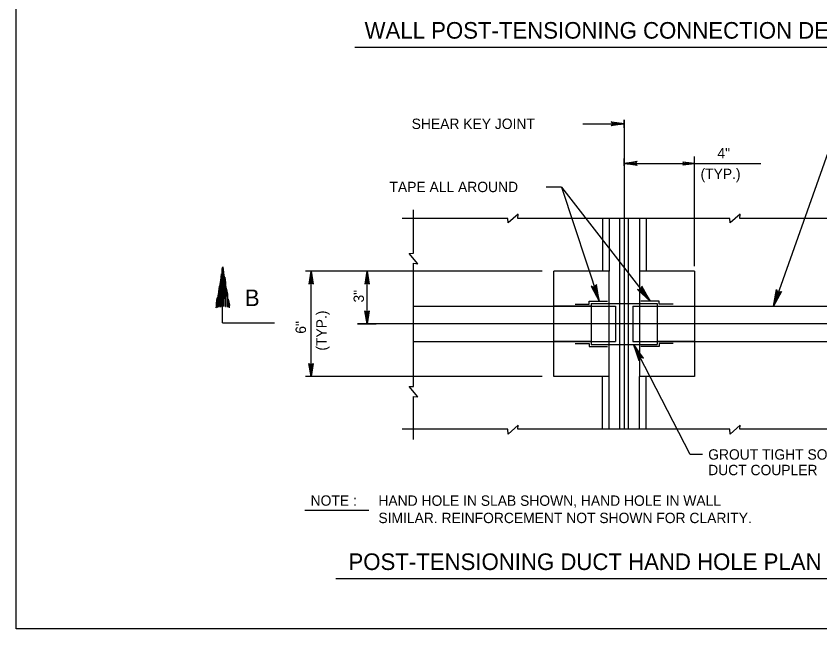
# Model space of a CAD drawing. Extents: x 641328 to 643024, y 298283 to 300065.
# Drawn here: x 642208.5 to 642441.2, y 298892.3 to 299069.6 of the extents above; entities that cross this region are included whole.
import ezdxf

# ---------------------------------------------------------------- set-up
doc = ezdxf.new("R2010")
doc.units = 0
doc.layers.add('2', color=7, linetype='Continuous')
doc.layers.add('Default', color=7, linetype='Continuous')

msp = doc.modelspace()

# ---------------------------------------------------------------- linework, layer by layer
at = {"layer": '2'}
for p, q in [((642208.51, 298892.3), (642208.51, 299456.3)), ((642306.6, 299060.56), (642498.06, 299060.56)), ((642384.54, 299039.59), (642384.54, 298950.05)), ((642372.57, 299038.42), (642384.54, 299038.42)), ((642380.93, 299038.85), (642380.74, 299039.01)), ((642380.74, 299039.01), (642384.54, 299038.42)), ((642384.54, 299038.42), (642380.74, 299037.79)), ((642380.74, 299037.79), (642380.94, 299037.96)), ((642380.93, 299038.85), (642381.06, 299038.59)), ((642384.54, 299038.42), (642380.93, 299038.85)), ((642380.94, 299037.96), (642384.54, 299038.42)), ((642381.07, 299038.23), (642380.94, 299037.96)), ((642381.06, 299038.59), (642384.54, 299038.42)), ((642381.06, 299038.59), (642381.07, 299038.23)), ((642384.54, 299038.42), (642381.06, 299038.41)), ((642384.54, 299038.42), (642381.07, 299038.23)), ((642443.48, 299030.02), (642427.76, 298985.61)), ((642404.86, 298997.23), (642404.86, 299028.92)), ((642384.54, 299026.92), (642388.33, 299027.55)), ((642388.14, 299027.38), (642384.54, 299026.92)), ((642384.54, 299026.92), (642388.01, 299027.12)), ((642384.54, 299026.92), (642388.01, 299026.93)), ((642384.54, 299026.92), (642424.12, 299026.92)), ((642388.01, 299026.75), (642384.54, 299026.92)), ((642384.54, 299026.92), (642388.15, 299026.49)), ((642388.34, 299026.33), (642384.54, 299026.92)), ((642388.01, 299027.12), (642388.14, 299027.38)), ((642388.01, 299026.75), (642388.01, 299027.12)), ((642388.15, 299026.49), (642388.01, 299026.75)), ((642388.33, 299027.55), (642388.14, 299027.38)), ((642388.15, 299026.49), (642388.34, 299026.33)), ((642366.39, 299020.08), (642377.29, 298987.09)), ((642366.39, 299020.08), (642392.02, 298987.09)), ((642323.58, 299000.94), (642323.58, 299013.53)), ((642350.88, 299011.01), (642320.28, 299011.01)), ((642415.14, 299011.01), (642353.77, 299011.01)), ((642378.28, 299011.01), (642378.28, 298995.77)), ((642380.19, 299011.01), (642380.19, 298995.77)), ((642383.27, 298986.45), (642383.27, 299011.01)), ((642385.81, 298986.45), (642385.81, 299011.01)), ((642388.98, 299011.01), (642388.98, 298995.77)), ((642390.89, 299011.01), (642390.89, 298995.77)), ((642448.79, 299011.01), (642418.02, 299011.01)), ((642323.58, 298962.42), (642323.58, 298998.05)), ((642268.29, 298980.82), (642268.29, 298995.86)), ((642360.81, 298995.77), (642292.3, 298995.77)), ((642293.33, 298991.97), (642293.92, 298995.77)), ((642293.92, 298995.77), (642293.49, 298992.16)), ((642293.75, 298992.29), (642293.92, 298995.77)), ((642293.92, 298965.29), (642293.92, 298995.77)), ((642293.92, 298995.77), (642294.12, 298992.3)), ((642294.38, 298992.17), (642293.92, 298995.77)), ((642293.92, 298995.77), (642294.55, 298991.97)), ((642293.92, 298995.77), (642293.94, 298992.3)), ((642309.52, 298991.97), (642310.11, 298995.77)), ((642310.11, 298995.77), (642309.68, 298992.16)), ((642309.95, 298992.29), (642310.11, 298995.77)), ((642310.11, 298980.53), (642310.11, 298995.77)), ((642310.11, 298995.77), (642310.31, 298992.3)), ((642310.57, 298992.17), (642310.11, 298995.77)), ((642310.11, 298995.77), (642310.75, 298991.97)), ((642310.11, 298995.77), (642310.13, 298992.3)), ((642364.22, 298965.29), (642364.22, 298995.77)), ((642380.19, 298995.77), (642364.22, 298995.77)), ((642380.19, 298986.45), (642380.19, 298995.77)), ((642404.86, 298995.77), (642388.98, 298995.77)), ((642388.98, 298995.77), (642388.98, 298986.45)), ((642404.86, 298995.77), (642404.86, 298965.29)), ((642293.49, 298992.16), (642293.33, 298991.97)), ((642293.49, 298992.16), (642293.75, 298992.29)), ((642293.75, 298992.29), (642294.12, 298992.3)), ((642294.12, 298992.3), (642294.38, 298992.17)), ((642294.55, 298991.97), (642294.38, 298992.17)), ((642309.68, 298992.16), (642309.52, 298991.97)), ((642309.68, 298992.16), (642309.95, 298992.29)), ((642309.95, 298992.29), (642310.31, 298992.3)), ((642310.31, 298992.3), (642310.57, 298992.17)), ((642310.75, 298991.97), (642310.57, 298992.17)), ((642370.35, 298986.24), (642374.38, 298986.24)), ((642374.38, 298986.24), (642374.38, 298987.09)), ((642374.38, 298987.09), (642379.73, 298987.09)), ((642375.01, 298986.45), (642394.06, 298986.45)), ((642375.01, 298986.45), (642375.01, 298974.6)), ((642380.19, 298974.6), (642380.19, 298986.45)), ((642383.27, 298974.6), (642383.27, 298986.45)), ((642385.81, 298974.6), (642385.81, 298986.45)), ((642388.98, 298986.45), (642388.98, 298974.6)), ((642394.7, 298987.09), (642389.34, 298987.09)), ((642394.06, 298986.45), (642394.06, 298974.6)), ((642394.7, 298986.24), (642394.7, 298987.09)), ((642398.73, 298986.24), (642394.7, 298986.24)), ((642310.11, 298980.53), (642309.48, 298984.32)), ((642309.48, 298984.32), (642309.65, 298984.13)), ((642309.92, 298984), (642309.65, 298984.13)), ((642309.65, 298984.13), (642310.11, 298980.53)), ((642310.11, 298980.53), (642309.92, 298984)), ((642310.28, 298984), (642309.92, 298984)), ((642310.11, 298980.53), (642310.1, 298984)), ((642310.7, 298984.33), (642310.11, 298980.53)), ((642310.11, 298980.53), (642310.54, 298984.14)), ((642310.28, 298984), (642310.11, 298980.53)), ((642310.54, 298984.14), (642310.28, 298984)), ((642310.54, 298984.14), (642310.7, 298984.33)), ((642323.58, 298985.61), (642382, 298985.61)), ((642375.01, 298985.61), (642364.22, 298985.61)), ((642382, 298985.61), (642382, 298975.45)), ((642387.08, 298985.61), (642445.37, 298985.61)), ((642387.08, 298985.61), (642387.08, 298975.45)), ((642394.06, 298985.61), (642404.86, 298985.61)), ((642268.29, 298980.82), (642283.32, 298980.82)), ((642456.43, 298980.53), (642307.36, 298980.53)), ((642307.36, 298980.53), (642312.7, 298980.53)), ((642323.58, 298975.45), (642382, 298975.45)), ((642375.01, 298975.45), (642364.22, 298975.45)), ((642370.35, 298974.81), (642374.38, 298974.81)), ((642374.38, 298974.81), (642374.38, 298973.97)), ((642375.01, 298974.6), (642394.06, 298974.6)), ((642380.19, 298965.29), (642380.19, 298974.6)), ((642383.27, 298950.05), (642383.27, 298974.6)), ((642385.81, 298950.05), (642385.81, 298974.6)), ((642387.08, 298975.45), (642445.37, 298975.45)), ((642403.61, 298942.76), (642387.25, 298974.6)), ((642388.98, 298974.6), (642388.98, 298965.29)), ((642404.86, 298975.45), (642394.06, 298975.45)), ((642398.73, 298974.81), (642394.7, 298974.81)), ((642394.7, 298974.81), (642394.7, 298973.97)), ((642374.38, 298973.97), (642379.73, 298973.97)), ((642394.7, 298973.97), (642389.34, 298973.97)), ((642293.92, 298965.29), (642293.29, 298969.08)), ((642293.29, 298969.08), (642293.46, 298968.89)), ((642293.72, 298968.76), (642293.46, 298968.89)), ((642293.46, 298968.89), (642293.92, 298965.29)), ((642293.92, 298965.29), (642293.72, 298968.76)), ((642294.09, 298968.76), (642293.72, 298968.76)), ((642293.92, 298965.29), (642293.91, 298968.76)), ((642294.51, 298969.09), (642293.92, 298965.29)), ((642293.92, 298965.29), (642294.35, 298968.9)), ((642294.09, 298968.76), (642293.92, 298965.29)), ((642294.35, 298968.9), (642294.09, 298968.76)), ((642294.35, 298968.9), (642294.51, 298969.09)), ((642360.81, 298965.29), (642292.3, 298965.29)), ((642380.19, 298965.29), (642364.22, 298965.29)), ((642378.28, 298950.05), (642378.28, 298965.29)), ((642380.19, 298950.05), (642380.19, 298965.29)), ((642404.86, 298965.29), (642388.98, 298965.29)), ((642388.98, 298950.05), (642388.98, 298965.29)), ((642390.89, 298950.05), (642390.89, 298965.29)), ((642323.58, 298947.06), (642323.58, 298959.52)), ((642350.88, 298950.05), (642320.28, 298950.05)), ((642415.14, 298950.05), (642353.77, 298950.05)), ((642448.79, 298950.05), (642418.02, 298950.05)), ((642292.06, 298926.66), (642310.66, 298926.66)), ((642301.08, 298906.86), (642474.41, 298906.86)), ((642994.5, 298892.3), (642208.51, 298892.3))]:
    msp.add_line(p, q, dxfattribs=at)
for points in [[(642384.54, 299039.59), (642384.54, 299039.59), (642384.54, 299037.26), (642384.54, 299037.26)], [(642384.54, 299028.38), (642384.54, 299028.38), (642384.54, 299026.22), (642384.54, 299026.22)]]:
    msp.add_lwpolyline(points, close=True, dxfattribs=at)
for points in [[(642401.61, 299027.29), (642401.73, 299027.04), (642404.86, 299026.92), (642401.61, 299027.29), (642401.48, 299027.42), (642404.86, 299026.92), (642401.73, 299026.79), (642401.61, 299026.54), (642404.86, 299026.92), (642401.48, 299026.42), (642401.61, 299026.54)], [(642353.77, 299011.01), (642353.89, 299012.28), (642350.92, 299009.73), (642350.88, 299011.01)], [(642418.02, 299011.01), (642418.15, 299012.28), (642415.18, 299009.73), (642415.14, 299011.01)], [(642323.66, 298998.05), (642324.82, 298997.93), (642322.27, 299000.9), (642323.58, 299000.94)], [(642270.32, 298985.13), (642268.34, 298997.01), (642266.36, 298985.13), (642266.56, 298985.33), (642266.56, 298986.51), (642266.76, 298988.1), (642266.76, 298985.33), (642267.16, 298985.52), (642267.16, 298989.88), (642267.35, 298991.46), (642267.35, 298985.52), (642267.75, 298985.52), (642267.75, 298993.05), (642267.95, 298995.03), (642267.95, 298985.52), (642268.15, 298985.52), (642268.15, 298996.41), (642268.34, 298997.01), (642268.54, 298995.42), (642268.54, 298985.72), (642268.74, 298985.52), (642268.94, 298994.04), (642269.14, 298992.45), (642269.14, 298985.52), (642269.33, 298985.52), (642269.33, 298990.87), (642269.73, 298989.09), (642269.73, 298985.52), (642269.93, 298985.33), (642269.93, 298987.7), (642270.32, 298985.92), (642270.13, 298985.33)], [(642375.29, 298991.29), (642375.66, 298991.23), (642377.29, 298987.09), (642375.29, 298991.29), (642375.03, 298991.45), (642377.29, 298987.09), (642376.11, 298991.37), (642376.37, 298991.63), (642377.29, 298987.09), (642376.5, 298991.94), (642376.37, 298991.63)], [(642388.73, 298990.38), (642389.1, 298990.45), (642392.02, 298987.09), (642388.73, 298990.38), (642388.43, 298990.44), (642392.02, 298987.09), (642389.47, 298990.73), (642389.63, 298991.06), (642392.02, 298987.09), (642389.65, 298991.39), (642389.63, 298991.06)], [(642429.85, 298989.76), (642429.47, 298989.71), (642427.76, 298985.61), (642429.85, 298989.76), (642430.12, 298989.92), (642427.76, 298985.61), (642429.04, 298989.86), (642428.78, 298990.13), (642427.76, 298985.61), (642428.65, 298990.44), (642428.78, 298990.13)], [(642389.87, 298970.76), (642389.49, 298970.76), (642387.25, 298974.6), (642389.87, 298970.76), (642390.16, 298970.64), (642387.25, 298974.6), (642389.08, 298970.55), (642388.86, 298970.26), (642387.25, 298974.6), (642388.78, 298969.94), (642388.86, 298970.26)], [(642323.66, 298959.52), (642324.82, 298959.4), (642322.27, 298962.37), (642323.58, 298962.42)], [(642353.78, 298950.05), (642353.89, 298951.21), (642350.92, 298948.66), (642350.88, 298950.05)], [(642418.03, 298950.05), (642418.15, 298951.21), (642415.18, 298948.66), (642415.13, 298950.05)]]:
    msp.add_lwpolyline(points, dxfattribs=at)
at = {"layer": 'Default'}
for p, q in [((642366.39, 299020.08), (642361.96, 299020.08)), ((642407.21, 298942.76), (642403.61, 298942.76))]:
    msp.add_line(p, q, dxfattribs=at)

# ---------------------------------------------------------------- texts
at = {"layer": '2'}
for s, height, p in [('WALL POST-TENSIONING CONNECTION DETAILS', 4.8, (642309.4, 299063.03)), ('  SHEAR KEY JOINT', 3, (642320.8, 299036.9)), ('4"', 3, (642411.54, 299028.42)), ('(TYP.)', 3, (642406.65, 299022.42)), ('TAPE ALL AROUND', 3, (642316.6, 299018.64)), ('B', 4.8, (642274.73, 298985.67)), ('GROUT TIGHT SOFT', 3, (642408.86, 298941.26)), ('DUCT COUPLER', 3, (642408.86, 298936.76)), ('NOTE :', 3, (642293.76, 298927.93)), ('HAND HOLE IN SLAB SHOWN, HAND HOLE IN WALL ', 3, (642313.39, 298927.9)), ('SIMILAR. REINFORCEMENT NOT SHOWN FOR CLARITY.', 3, (642313.39, 298922.9)), ('POST-TENSIONING DUCT HAND HOLE PLAN', 4.8, (642304.73, 298909.34))]:
    msp.add_text(s, height=height, dxfattribs=at).set_placement(p)
for s, p in [('3"', (642309.2, 298986.7)), ('(TYP.)', (642298.42, 298972.79)), ('6"', (642292.42, 298977.68))]:
    msp.add_text(s, height=3, rotation=90, dxfattribs=at).set_placement(p)

doc.saveas('drawing.dxf')
